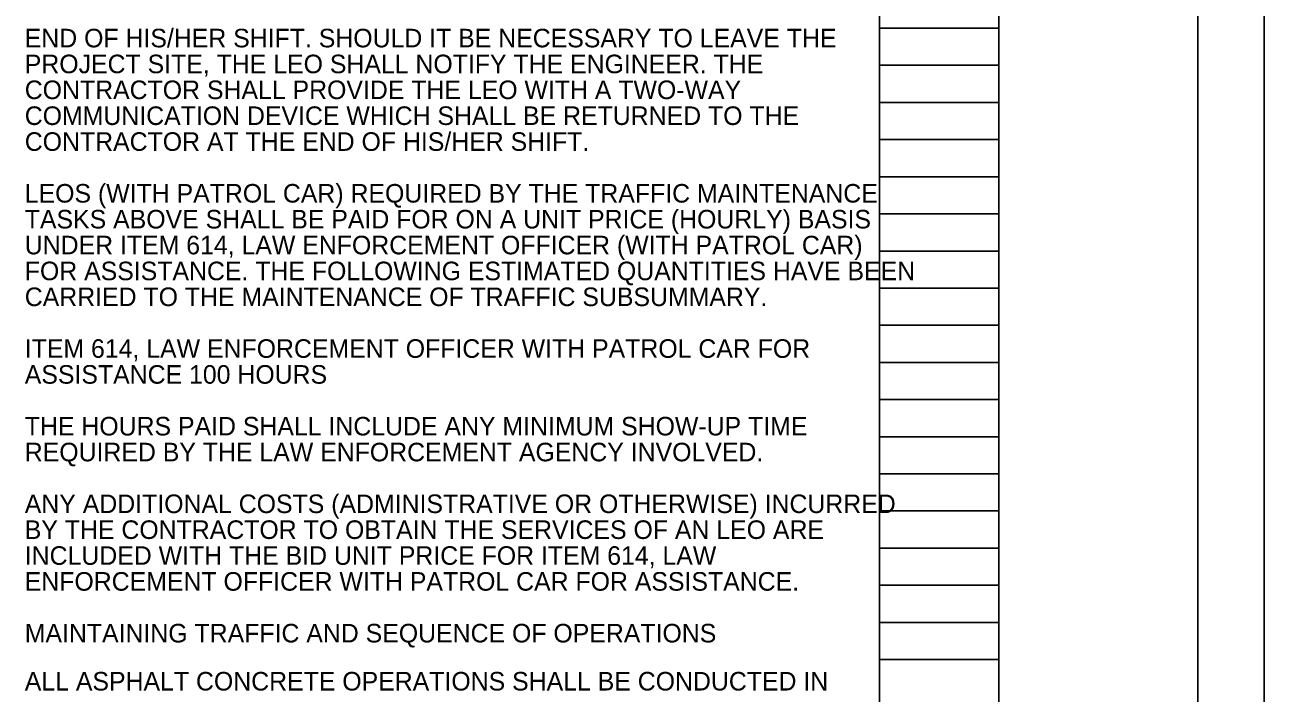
# Model space of a CAD drawing. Extents: x 0 to 34, y 0 to 22.
# Drawn here: x 24.66 to 34, y 5.21 to 10.25 of the extents above; entities that cross this region are included whole.
import ezdxf

# ---------------------------------------------------------------- set-up
doc = ezdxf.new("R2010")
doc.units = 0
for name, color, linetype in [('SH_Border', 7, 'Continuous'), ('SH_Cut_Line', 7, 'Continuous'), ('SH_Data', 7, 'Continuous'), ('SH_Text', 7, 'Continuous')]:
    doc.layers.add(name, color=color, linetype=linetype)

msp = doc.modelspace()

# ---------------------------------------------------------------- linework, layer by layer
at = {"layer": 'SH_Border'}
msp.add_line((32, 0.5), (32, 21.5), dxfattribs=at)
msp.add_lwpolyline([(1.5, 21.5), (33.5, 21.5), (33.5, 0.5), (1.5, 0.5)], close=True, dxfattribs=at)
at = {"layer": 'SH_Cut_Line'}
msp.add_lwpolyline([(0, 0), (34, 0), (34, 22), (0, 22)], close=True, dxfattribs=at)
at = {"layer": 'SH_Data'}
for p, q in [((31.1, 0.98), (31.1, 21.14)), ((32, 0.98), (32, 21.14)), ((31.1, 10.22), (32, 10.22)), ((31.1, 9.94), (32, 9.94)), ((31.1, 9.66), (32, 9.66)), ((31.1, 9.38), (32, 9.38)), ((31.1, 9.1), (32, 9.1)), ((31.1, 8.82), (32, 8.82)), ((31.1, 8.54), (32, 8.54)), ((31.1, 8.26), (32, 8.26)), ((31.1, 7.98), (32, 7.98)), ((31.1, 7.7), (32, 7.7)), ((31.1, 7.42), (32, 7.42)), ((31.1, 7.14), (32, 7.14)), ((31.1, 6.86), (32, 6.86)), ((31.1, 6.58), (32, 6.58)), ((31.1, 6.3), (32, 6.3)), ((31.1, 6.02), (32, 6.02)), ((31.1, 5.74), (32, 5.74)), ((31.1, 5.46), (32, 5.46))]:
    msp.add_line(p, q, dxfattribs=at)

# ---------------------------------------------------------------- texts
at = {"layer": 'SH_Text'}
for s, p in [('END OF HIS/HER SHIFT. SHOULD IT BE NECESSARY TO LEAVE THE ', (24.66, 10.0755)), ('PROJECT SITE, THE LEO SHALL NOTIFY THE ENGINEER. THE ', (24.66, 9.8805)), ('CONTRACTOR SHALL PROVIDE THE LEO WITH A TWO-WAY ', (24.66, 9.6854)), ('COMMUNICATION DEVICE WHICH SHALL BE RETURNED TO THE ', (24.66, 9.4903)), ('CONTRACTOR AT THE END OF HIS/HER SHIFT. ', (24.66, 9.2952)), ('LEOS (WITH PATROL CAR) REQUIRED BY THE TRAFFIC MAINTENANCE ', (24.66, 8.9051)), ('TASKS ABOVE SHALL BE PAID FOR ON A UNIT PRICE (HOURLY) BASIS ', (24.66, 8.71)), ('UNDER ITEM 614, LAW ENFORCEMENT OFFICER (WITH PATROL CAR) ', (24.66, 8.5149)), ('FOR ASSISTANCE. THE FOLLOWING ESTIMATED QUANTITIES HAVE BEEN ', (24.66, 8.3198)), ('CARRIED TO THE MAINTENANCE OF TRAFFIC SUBSUMMARY. ', (24.66, 8.1247)), ('ITEM 614, LAW ENFORCEMENT OFFICER WITH PATROL CAR FOR ', (24.66, 7.7346)), ('ASSISTANCE 100 HOURS ', (24.66, 7.5395)), ('THE HOURS PAID SHALL INCLUDE ANY MINIMUM SHOW-UP TIME ', (24.66, 7.1493)), ('REQUIRED BY THE LAW ENFORCEMENT AGENCY INVOLVED. ', (24.66, 6.9543)), ('ANY ADDITIONAL COSTS (ADMINISTRATIVE OR OTHERWISE) INCURRED ', (24.66, 6.5641)), ('BY THE CONTRACTOR TO OBTAIN THE SERVICES OF AN LEO ARE ', (24.66, 6.369)), ('INCLUDED WITH THE BID UNIT PRICE FOR ITEM 614, LAW ', (24.66, 6.1739)), ('ENFORCEMENT OFFICER WITH PATROL CAR FOR ASSISTANCE.', (24.66, 5.9789)), ('MAINTAINING TRAFFIC AND SEQUENCE OF OPERATIONS', (24.66, 5.5887)), ('ALL ASPHALT CONCRETE OPERATIONS SHALL BE CONDUCTED IN ', (24.66, 5.2263))]:
    msp.add_text(s, height=0.14, dxfattribs=at).set_placement(p)

doc.saveas('drawing.dxf')
